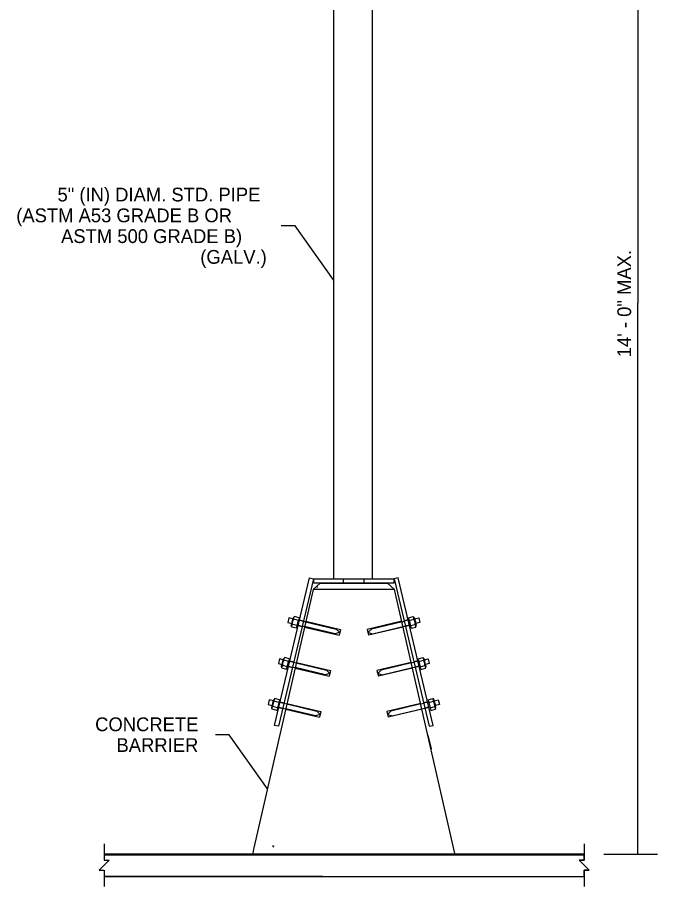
# Model space of a CAD drawing. Extents: x 99988 to 100172, y 99995 to 100047.
# Drawn here: x 100006.354 to 100009.611, y 100001.519 to 100005.936 of the extents above; entities that cross this region are included whole.
import ezdxf

# ---------------------------------------------------------------- set-up
doc = ezdxf.new("R2010")
doc.units = 0
for name, color, linetype in [('Level 1', 7, 'Continuous'), ('Level 10', 7, 'Continuous'), ('Level 12', 7, 'Continuous'), ('Level 15', 7, 'Continuous'), ('Level 18', 7, 'Continuous'), ('Level 20', 7, 'Continuous'), ('Level 8', 7, 'Continuous')]:
    doc.layers.add(name, color=color, linetype=linetype)

msp = doc.modelspace()

# ---------------------------------------------------------------- linework, layer by layer
at = {"layer": 'Level 1'}
msp.add_line((100006.796, 100001.681), (100009.2374, 100001.681), dxfattribs=at)
for points in [[(100007.9087, 100001.571), (100006.796, 100001.571)], [(100006.796, 100001.571), (100009.2374, 100001.571)]]:
    msp.add_lwpolyline(points, dxfattribs=at)
at = {"layer": 'Level 10'}
for p, q in [((100008.1604, 100003.0822), (100008.1604, 100007.3213)), ((100007.9616, 100007.3133), (100007.9616, 100003.0822))]:
    msp.add_line(p, q, dxfattribs=at)
at = {"layer": 'Level 12'}
for p, q in [((100007.8621, 100003.0822), (100008.2692, 100003.0822)), ((100007.8621, 100003.0607), (100007.8621, 100003.0822)), ((100008.0121, 100003.0822), (100008.0121, 100003.0607)), ((100008.1192, 100003.0607), (100008.1192, 100003.0822)), ((100008.2692, 100003.0822), (100008.2692, 100003.0607)), ((100008.2692, 100003.0607), (100007.8621, 100003.0607)), ((100008.1192, 100003.0607), (100008.0121, 100003.0607))]:
    msp.add_line(p, q, dxfattribs=at)
for points in [[(100007.861, 100003.0834), (100007.6826, 100002.3333), (100007.6618, 100002.3382), (100007.8401, 100003.0884)], [(100008.2703, 100003.0834), (100008.4487, 100002.3333), (100008.4695, 100002.3382), (100008.2912, 100003.0884)]]:
    msp.add_lwpolyline(points, close=True, dxfattribs=at)
at = {"layer": 'Level 15'}
for p, q in [((100009.511, 100007.2852), (100009.511, 100004.4843)), ((100009.511, 100001.6835), (100009.511, 100004.4843)), ((100009.3374, 100001.6835), (100009.611, 100001.6835))]:
    msp.add_line(p, q, dxfattribs=at)
for points in [[(100007.9616, 100004.6015), (100007.7669, 100004.8769), (100007.6969, 100004.8769)], [(100007.6262, 100002.0153), (100007.4314, 100002.2907), (100007.3614, 100002.2907)], [(100006.796, 100001.7357), (100006.796, 100001.6525), (100006.8213, 100001.6525), (100006.7707, 100001.602), (100006.796, 100001.602), (100006.796, 100001.5188)], [(100009.2374, 100001.7357), (100009.2374, 100001.6525), (100009.2122, 100001.6525), (100009.2627, 100001.602), (100009.2374, 100001.602), (100009.2374, 100001.5188)], [(100009.2374, 100001.7357), (100009.2374, 100001.6525), (100009.2122, 100001.6525), (100009.2627, 100001.602), (100009.2374, 100001.602), (100009.2374, 100001.5188)]]:
    msp.add_lwpolyline(points, dxfattribs=at)
at = {"layer": 'Level 18'}
for p, q in [((100007.9799, 100003.0822), (100008.1514, 100003.0822)), ((100008.146, 100003.0822), (100008.1514, 100003.0822)), ((100007.7352, 100002.8851), (100007.7294, 100002.8608)), ((100007.7294, 100002.8608), (100007.7501, 100002.8558)), ((100007.7562, 100002.8801), (100007.7352, 100002.8851)), ((100007.7842, 100002.8734), (100007.7887, 100002.8723)), ((100007.7887, 100002.8723), (100007.8096, 100002.8674)), ((100007.8096, 100002.8674), (100007.8206, 100002.8647)), ((100007.8206, 100002.8647), (100007.9763, 100002.8277)), ((100008.3108, 100002.8647), (100008.1551, 100002.8277)), ((100008.3108, 100002.8647), (100008.3218, 100002.8674)), ((100008.3427, 100002.8723), (100008.3218, 100002.8674)), ((100008.3472, 100002.8734), (100008.3427, 100002.8723)), ((100008.3752, 100002.8801), (100008.3963, 100002.8851)), ((100008.402, 100002.8608), (100008.3813, 100002.8558)), ((100008.3963, 100002.8851), (100008.402, 100002.8608)), ((100007.7781, 100002.8491), (100007.783, 100002.848)), ((100007.783, 100002.848), (100007.8038, 100002.843)), ((100007.8038, 100002.843), (100007.8151, 100002.8404)), ((100007.9705, 100002.8034), (100007.8151, 100002.8404)), ((100007.9915, 100002.8099), (100007.9705, 100002.8034)), ((100007.9763, 100002.8277), (100007.9921, 100002.8124)), ((100008.1551, 100002.8277), (100008.1393, 100002.8124)), ((100008.1399, 100002.8099), (100008.1609, 100002.8034)), ((100008.1609, 100002.8034), (100008.3164, 100002.8404)), ((100008.3164, 100002.8404), (100008.3276, 100002.843)), ((100008.3485, 100002.848), (100008.3276, 100002.843)), ((100008.3533, 100002.8491), (100008.3485, 100002.848)), ((100007.688, 100002.6762), (100007.6822, 100002.6519)), ((100007.6822, 100002.6519), (100007.7013, 100002.6473)), ((100007.7069, 100002.6717), (100007.688, 100002.6762)), ((100007.7285, 100002.6407), (100007.7334, 100002.6395)), ((100007.7334, 100002.6395), (100007.7542, 100002.6346)), ((100007.7346, 100002.6649), (100007.7392, 100002.6639)), ((100007.7392, 100002.6639), (100007.76, 100002.6589)), ((100007.7542, 100002.6346), (100007.7672, 100002.6315)), ((100007.76, 100002.6589), (100007.7728, 100002.6559)), ((100007.7728, 100002.6559), (100007.9268, 100002.6193)), ((100008.3586, 100002.6559), (100008.2047, 100002.6193)), ((100008.3586, 100002.6559), (100008.3714, 100002.6589)), ((100008.3642, 100002.6315), (100008.3772, 100002.6346)), ((100008.3922, 100002.6639), (100008.3714, 100002.6589)), ((100008.398, 100002.6395), (100008.3772, 100002.6346)), ((100008.3968, 100002.6649), (100008.3922, 100002.6639)), ((100008.4029, 100002.6407), (100008.398, 100002.6395)), ((100008.4245, 100002.6717), (100008.4434, 100002.6762)), ((100008.4492, 100002.6519), (100008.4302, 100002.6473)), ((100008.4434, 100002.6762), (100008.4492, 100002.6519)), ((100007.921, 100002.5949), (100007.7672, 100002.6315)), ((100007.942, 100002.6015), (100007.921, 100002.5949)), ((100007.9268, 100002.6193), (100007.9426, 100002.604)), ((100008.2047, 100002.6193), (100008.1889, 100002.604)), ((100008.1894, 100002.6015), (100008.2104, 100002.5949)), ((100008.2104, 100002.5949), (100008.3642, 100002.6315)), ((100007.636, 100002.4682), (100007.6302, 100002.4438)), ((100007.657, 100002.4632), (100007.636, 100002.4682)), ((100007.6849, 100002.4565), (100007.6894, 100002.4555)), ((100008.4466, 100002.4565), (100008.4421, 100002.4555)), ((100008.4744, 100002.4632), (100008.4954, 100002.4682)), ((100008.4954, 100002.4682), (100008.5012, 100002.4438)), ((100007.6302, 100002.4438), (100007.6509, 100002.4389)), ((100007.6786, 100002.4323), (100007.6836, 100002.4311)), ((100007.6836, 100002.4311), (100007.7044, 100002.4262)), ((100007.6894, 100002.4555), (100007.7102, 100002.4505)), ((100007.7044, 100002.4262), (100007.7194, 100002.4226)), ((100007.7102, 100002.4505), (100007.725, 100002.447)), ((100007.8712, 100002.3866), (100007.7194, 100002.4226)), ((100007.725, 100002.447), (100007.877, 100002.4109)), ((100008.4064, 100002.447), (100008.2545, 100002.4109)), ((100008.2603, 100002.3866), (100008.412, 100002.4226)), ((100008.4064, 100002.447), (100008.4212, 100002.4505)), ((100008.412, 100002.4226), (100008.427, 100002.4262)), ((100008.4421, 100002.4555), (100008.4212, 100002.4505)), ((100008.4478, 100002.4311), (100008.427, 100002.4262)), ((100008.4528, 100002.4323), (100008.4478, 100002.4311)), ((100008.5012, 100002.4438), (100008.4805, 100002.4389)), ((100007.8922, 100002.3931), (100007.8712, 100002.3866)), ((100007.877, 100002.4109), (100007.8928, 100002.3956)), ((100008.2545, 100002.4109), (100008.2387, 100002.3956)), ((100008.2393, 100002.3931), (100008.2603, 100002.3866))]:
    msp.add_line(p, q, dxfattribs=at)
for centre, start, end in [((100007.9911, 100002.8113), 287.2722, 45.9747), ((100008.1403, 100002.8113), 134.0253, 252.7278), ((100007.9415, 100002.6029), 287.2722, 45.9747), ((100008.1899, 100002.6029), 134.0253, 252.7278), ((100007.8917, 100002.3945), 287.2722, 45.9747), ((100008.2397, 100002.3945), 134.0253, 252.7278)]:
    msp.add_arc(centre, 0.0015, start, end, dxfattribs=at)
at = {"layer": 'Level 20'}
for p, q in [((100007.7477, 100002.8455), (100007.75, 100002.8545)), ((100007.7638, 100002.8912), (100007.7576, 100002.8851)), ((100007.7838, 100002.8717), (100007.7605, 100002.8775)), ((100007.7872, 100002.8853), (100007.7639, 100002.8911)), ((100007.7769, 100002.8445), (100007.7838, 100002.8719)), ((100007.7838, 100002.8717), (100007.777, 100002.8448)), ((100007.7872, 100002.8853), (100007.7838, 100002.8717)), ((100007.7871, 100002.8854), (100007.7871, 100002.8853)), ((100007.7893, 100002.8747), (100007.8102, 100002.8698)), ((100007.8212, 100002.8672), (100007.9974, 100002.8253)), ((100008.3102, 100002.8672), (100008.134, 100002.8253)), ((100008.3421, 100002.8747), (100008.3213, 100002.8698)), ((100008.3443, 100002.8853), (100008.3676, 100002.8911)), ((100008.3443, 100002.8853), (100008.3477, 100002.8717)), ((100008.3444, 100002.8854), (100008.3444, 100002.8853)), ((100008.3545, 100002.8445), (100008.3476, 100002.8719)), ((100008.3477, 100002.8717), (100008.371, 100002.8775)), ((100008.3477, 100002.8717), (100008.3544, 100002.8448)), ((100008.3676, 100002.8912), (100008.3738, 100002.8851)), ((100008.3837, 100002.8455), (100008.3815, 100002.8545)), ((100007.7736, 100002.8313), (100007.7503, 100002.8371)), ((100007.777, 100002.8448), (100007.7537, 100002.8507)), ((100007.777, 100002.8448), (100007.7736, 100002.8313)), ((100007.7736, 100002.8313), (100007.7769, 100002.8445)), ((100007.7824, 100002.8456), (100007.8032, 100002.8406)), ((100007.8145, 100002.8379), (100007.9905, 100002.7961)), ((100007.9974, 100002.8253), (100007.9905, 100002.7961)), ((100008.134, 100002.8253), (100008.1409, 100002.7961)), ((100008.3169, 100002.8379), (100008.1409, 100002.7961)), ((100008.3491, 100002.8456), (100008.3282, 100002.8406)), ((100008.3544, 100002.8448), (100008.3777, 100002.8507)), ((100008.3544, 100002.8448), (100008.3578, 100002.8313)), ((100008.3578, 100002.8313), (100008.3545, 100002.8445)), ((100008.3578, 100002.8313), (100008.3811, 100002.8371)), ((100007.7142, 100002.6827), (100007.7081, 100002.6766)), ((100007.7376, 100002.6768), (100007.7143, 100002.6827)), ((100007.7376, 100002.6768), (100007.7342, 100002.6633)), ((100007.7375, 100002.6769), (100007.7375, 100002.6768)), ((100008.3938, 100002.6768), (100008.4171, 100002.6827)), ((100008.3938, 100002.6768), (100008.3972, 100002.6633)), ((100008.3939, 100002.6769), (100008.3939, 100002.6768)), ((100008.4172, 100002.6827), (100008.4234, 100002.6766)), ((100007.6982, 100002.6371), (100007.7004, 100002.6461)), ((100007.7275, 100002.6364), (100007.7042, 100002.6422)), ((100007.7342, 100002.6633), (100007.7109, 100002.6691)), ((100007.7275, 100002.6364), (100007.7241, 100002.6228)), ((100007.7241, 100002.6228), (100007.7274, 100002.636)), ((100007.7274, 100002.636), (100007.7342, 100002.6634)), ((100007.7342, 100002.6633), (100007.7275, 100002.6364)), ((100007.7328, 100002.6371), (100007.7537, 100002.6321)), ((100007.7398, 100002.6663), (100007.7606, 100002.6613)), ((100007.7734, 100002.6583), (100007.9479, 100002.6168)), ((100008.3581, 100002.6583), (100008.1836, 100002.6168)), ((100008.3917, 100002.6663), (100008.3708, 100002.6613)), ((100008.3986, 100002.6371), (100008.3778, 100002.6321)), ((100008.3972, 100002.6633), (100008.4205, 100002.6691)), ((100008.4041, 100002.636), (100008.3972, 100002.6634)), ((100008.3972, 100002.6633), (100008.404, 100002.6364)), ((100008.404, 100002.6364), (100008.4273, 100002.6422)), ((100008.404, 100002.6364), (100008.4074, 100002.6228)), ((100008.4074, 100002.6228), (100008.4041, 100002.636)), ((100008.4333, 100002.6371), (100008.431, 100002.6461)), ((100007.7241, 100002.6228), (100007.7008, 100002.6287)), ((100007.7667, 100002.6291), (100007.9409, 100002.5876)), ((100007.9479, 100002.6168), (100007.9409, 100002.5876)), ((100008.1836, 100002.6168), (100008.1905, 100002.5876)), ((100008.3648, 100002.6291), (100008.1905, 100002.5876)), ((100008.4074, 100002.6228), (100008.4306, 100002.6287)), ((100007.6363, 100002.4694), (100007.6363, 100002.4694)), ((100007.6573, 100002.4644), (100007.6583, 100002.4682)), ((100007.6644, 100002.4744), (100007.6583, 100002.4682)), ((100007.6844, 100002.4549), (100007.6611, 100002.4607)), ((100007.6878, 100002.4684), (100007.6645, 100002.4743)), ((100007.6878, 100002.4684), (100007.6844, 100002.4549)), ((100007.6877, 100002.4685), (100007.6877, 100002.4685)), ((100007.69, 100002.4579), (100007.7108, 100002.4529)), ((100008.4415, 100002.4579), (100008.4206, 100002.4529)), ((100008.4436, 100002.4684), (100008.4669, 100002.4743)), ((100008.4436, 100002.4684), (100008.447, 100002.4549)), ((100008.4437, 100002.4685), (100008.4437, 100002.4685)), ((100008.447, 100002.4549), (100008.4703, 100002.4607)), ((100008.467, 100002.4744), (100008.4732, 100002.4682)), ((100008.4741, 100002.4644), (100008.4732, 100002.4682)), ((100008.4952, 100002.4694), (100008.4952, 100002.4694)), ((100007.6484, 100002.4287), (100007.6506, 100002.4377)), ((100007.6743, 100002.4144), (100007.651, 100002.4203)), ((100007.6777, 100002.428), (100007.6544, 100002.4338)), ((100007.6777, 100002.428), (100007.6743, 100002.4144)), ((100007.6844, 100002.4549), (100007.6777, 100002.428)), ((100007.683, 100002.4287), (100007.7039, 100002.4238)), ((100007.7189, 100002.4202), (100007.8911, 100002.3792)), ((100007.7256, 100002.4494), (100007.8981, 100002.4084)), ((100008.4059, 100002.4494), (100008.2334, 100002.4084)), ((100008.4126, 100002.4202), (100008.2403, 100002.3792)), ((100008.4484, 100002.4287), (100008.4276, 100002.4238)), ((100008.447, 100002.4549), (100008.4538, 100002.428)), ((100008.4538, 100002.428), (100008.4771, 100002.4338)), ((100008.4538, 100002.428), (100008.4572, 100002.4144)), ((100008.4572, 100002.4144), (100008.4804, 100002.4203)), ((100008.4831, 100002.4287), (100008.4808, 100002.4377)), ((100007.8981, 100002.4084), (100007.8911, 100002.3792)), ((100008.2334, 100002.4084), (100008.2403, 100002.3792))]:
    msp.add_line(p, q, dxfattribs=at)
msp.add_lwpolyline([(100007.9087, 100001.571), (100009.2374, 100001.571), (100009.2374, 100001.602), (100009.2627, 100001.602), (100009.2122, 100001.6525), (100009.2374, 100001.6525), (100009.2374, 100001.6835), (100008.9538, 100001.6835), (100008.7339, 100001.6835), (100008.367, 100001.6835), (100007.6568, 100001.6835), (100007.2898, 100001.6835), (100007.1618, 100001.6835), (100006.796, 100001.6835), (100006.796, 100001.6525), (100006.8213, 100001.6525), (100006.7707, 100001.602), (100006.796, 100001.602), (100006.796, 100001.571), (100007.9087, 100001.571)], dxfattribs=at)
for points, degree in [([(100007.75, 100002.8545), (100007.75, 100002.8545), (100007.7567, 100002.8812), (100007.7576, 100002.8851), (100007.7567, 100002.8812), (100007.75, 100002.8545), (100007.75, 100002.8545)], 4), ([(100007.7537, 100002.8507), (100007.7535, 100002.8554), (100007.7538, 100002.86), (100007.7561, 100002.8692), (100007.7581, 100002.8735), (100007.7605, 100002.8775)], 3), ([(100007.7605, 100002.8775), (100007.7597, 100002.8801), (100007.7594, 100002.8825), (100007.7606, 100002.8872), (100007.762, 100002.8892), (100007.7639, 100002.8911)], 3), ([(100007.7605, 100002.8775), (100007.7597, 100002.8801), (100007.7594, 100002.8825), (100007.7606, 100002.8872), (100007.762, 100002.8892), (100007.7639, 100002.8911)], 3), ([(100008.371, 100002.8775), (100008.3717, 100002.8801), (100008.372, 100002.8825), (100008.3709, 100002.8872), (100008.3694, 100002.8892), (100008.3676, 100002.8911)], 3), ([(100008.371, 100002.8775), (100008.3717, 100002.8801), (100008.372, 100002.8825), (100008.3709, 100002.8872), (100008.3694, 100002.8892), (100008.3676, 100002.8911)], 3), ([(100008.3777, 100002.8507), (100008.3779, 100002.8554), (100008.3776, 100002.86), (100008.3754, 100002.8692), (100008.3734, 100002.8735), (100008.371, 100002.8775)], 3), ([(100008.3815, 100002.8545), (100008.3815, 100002.8545), (100008.3748, 100002.8812), (100008.3738, 100002.8851), (100008.3748, 100002.8812), (100008.3815, 100002.8545), (100008.3815, 100002.8545)], 4), ([(100007.7502, 100002.8373), (100007.7494, 100002.84), (100007.7486, 100002.8428), (100007.7477, 100002.8455)], 2), ([(100007.7503, 100002.8371), (100007.7496, 100002.8396), (100007.7493, 100002.8421), (100007.7504, 100002.8467), (100007.7518, 100002.8488), (100007.7537, 100002.8507)], 3), ([(100007.7503, 100002.8371), (100007.7496, 100002.8396), (100007.7493, 100002.8421), (100007.7504, 100002.8467), (100007.7518, 100002.8488), (100007.7537, 100002.8507)], 3), ([(100008.3811, 100002.8371), (100008.3819, 100002.8396), (100008.3822, 100002.8421), (100008.381, 100002.8467), (100008.3796, 100002.8488), (100008.3777, 100002.8507)], 3), ([(100008.3811, 100002.8371), (100008.3819, 100002.8396), (100008.3822, 100002.8421), (100008.381, 100002.8467), (100008.3796, 100002.8488), (100008.3777, 100002.8507)], 3), ([(100008.3812, 100002.8373), (100008.382, 100002.84), (100008.3829, 100002.8428), (100008.3837, 100002.8455)], 2), ([(100007.7109, 100002.6691), (100007.7101, 100002.6716), (100007.7098, 100002.6741), (100007.711, 100002.6787), (100007.7124, 100002.6808), (100007.7143, 100002.6827)], 3), ([(100007.7109, 100002.6691), (100007.7101, 100002.6716), (100007.7098, 100002.6741), (100007.711, 100002.6787), (100007.7124, 100002.6808), (100007.7143, 100002.6827)], 3), ([(100008.4205, 100002.6691), (100008.4213, 100002.6716), (100008.4216, 100002.6741), (100008.4204, 100002.6787), (100008.419, 100002.6808), (100008.4171, 100002.6827)], 3), ([(100008.4205, 100002.6691), (100008.4213, 100002.6716), (100008.4216, 100002.6741), (100008.4204, 100002.6787), (100008.419, 100002.6808), (100008.4171, 100002.6827)], 3), ([(100007.7007, 100002.6289), (100007.6998, 100002.6316), (100007.699, 100002.6343), (100007.6982, 100002.6371)], 2), ([(100007.7008, 100002.6287), (100007.7, 100002.6312), (100007.6997, 100002.6337), (100007.7009, 100002.6383), (100007.7023, 100002.6403), (100007.7042, 100002.6422)], 3), ([(100007.7008, 100002.6287), (100007.7, 100002.6312), (100007.6997, 100002.6337), (100007.7009, 100002.6383), (100007.7023, 100002.6403), (100007.7042, 100002.6422)], 3), ([(100007.7004, 100002.6461), (100007.7004, 100002.6461), (100007.7033, 100002.6578), (100007.7081, 100002.6766)], 3), ([(100007.7042, 100002.6422), (100007.704, 100002.6469), (100007.7042, 100002.6516), (100007.7065, 100002.6607), (100007.7085, 100002.665), (100007.7109, 100002.6691)], 3), ([(100007.7046, 100002.6627), (100007.7046, 100002.6626), (100007.7046, 100002.6626), (100007.7046, 100002.6626)], 3), ([(100008.4273, 100002.6422), (100008.4275, 100002.6469), (100008.4272, 100002.6516), (100008.4249, 100002.6607), (100008.4229, 100002.665), (100008.4205, 100002.6691)], 3), ([(100008.431, 100002.6461), (100008.431, 100002.6461), (100008.4281, 100002.6578), (100008.4234, 100002.6766)], 3), ([(100008.4269, 100002.6627), (100008.4269, 100002.6626), (100008.4269, 100002.6626), (100008.4269, 100002.6626)], 3), ([(100008.4306, 100002.6287), (100008.4314, 100002.6312), (100008.4317, 100002.6337), (100008.4306, 100002.6383), (100008.4291, 100002.6403), (100008.4273, 100002.6422)], 3), ([(100008.4306, 100002.6287), (100008.4314, 100002.6312), (100008.4317, 100002.6337), (100008.4306, 100002.6383), (100008.4291, 100002.6403), (100008.4273, 100002.6422)], 3), ([(100008.4308, 100002.6289), (100008.4316, 100002.6316), (100008.4324, 100002.6343), (100008.4333, 100002.6371)], 2), ([(100007.6506, 100002.4377), (100007.6506, 100002.4377), (100007.6573, 100002.4644), (100007.6573, 100002.4644), (100007.6573, 100002.4644), (100007.6506, 100002.4377), (100007.6506, 100002.4377)], 4), ([(100007.6544, 100002.4338), (100007.6542, 100002.4385), (100007.6544, 100002.4432), (100007.6567, 100002.4524), (100007.6587, 100002.4567), (100007.6611, 100002.4607)], 3), ([(100007.6611, 100002.4607), (100007.6603, 100002.4633), (100007.66, 100002.4657), (100007.6612, 100002.4703), (100007.6626, 100002.4724), (100007.6645, 100002.4743)], 3), ([(100007.6611, 100002.4607), (100007.6603, 100002.4633), (100007.66, 100002.4657), (100007.6612, 100002.4703), (100007.6626, 100002.4724), (100007.6645, 100002.4743)], 3), ([(100008.4703, 100002.4607), (100008.4711, 100002.4633), (100008.4714, 100002.4657), (100008.4702, 100002.4703), (100008.4688, 100002.4724), (100008.4669, 100002.4743)], 3), ([(100008.4703, 100002.4607), (100008.4711, 100002.4633), (100008.4714, 100002.4657), (100008.4702, 100002.4703), (100008.4688, 100002.4724), (100008.4669, 100002.4743)], 3), ([(100008.4771, 100002.4338), (100008.4773, 100002.4385), (100008.477, 100002.4432), (100008.4747, 100002.4524), (100008.4727, 100002.4567), (100008.4703, 100002.4607)], 3), ([(100008.4808, 100002.4377), (100008.4808, 100002.4377), (100008.4741, 100002.4644), (100008.4741, 100002.4644), (100008.4741, 100002.4644), (100008.4808, 100002.4377), (100008.4808, 100002.4377)], 4), ([(100007.6509, 100002.4205), (100007.65, 100002.4232), (100007.6492, 100002.4259), (100007.6484, 100002.4287)], 2), ([(100007.651, 100002.4203), (100007.6502, 100002.4228), (100007.6499, 100002.4253), (100007.6511, 100002.4299), (100007.6525, 100002.4319), (100007.6544, 100002.4338)], 3), ([(100007.651, 100002.4203), (100007.6502, 100002.4228), (100007.6499, 100002.4253), (100007.6511, 100002.4299), (100007.6525, 100002.4319), (100007.6544, 100002.4338)], 3), ([(100008.4804, 100002.4203), (100008.4812, 100002.4228), (100008.4815, 100002.4253), (100008.4804, 100002.4299), (100008.479, 100002.4319), (100008.4771, 100002.4338)], 3), ([(100008.4804, 100002.4203), (100008.4812, 100002.4228), (100008.4815, 100002.4253), (100008.4804, 100002.4299), (100008.479, 100002.4319), (100008.4771, 100002.4338)], 3), ([(100008.4806, 100002.4205), (100008.4814, 100002.4232), (100008.4822, 100002.4259), (100008.4831, 100002.4287)], 2)]:
    msp.add_open_spline(points, degree=degree, dxfattribs=at)
at = {"layer": 'Level 8'}
for p, q in [((100007.8582, 100003.0286), (100007.8943, 100003.0605)), ((100007.8943, 100003.0605), (100007.8774, 100003.0455)), ((100007.8825, 100003.0391), (100007.8774, 100003.0455)), ((100007.8943, 100003.0605), (100008.2371, 100003.0605)), ((100008.254, 100003.0456), (100008.2371, 100003.0605)), ((100008.2371, 100003.0605), (100008.2733, 100003.0286)), ((100008.2733, 100003.0286), (100007.8582, 100003.0286)), ((100008.4426, 100002.289), (100008.4587, 100002.2189)), ((100007.6544, 100001.7282), (100007.653, 100001.7223)), ((100007.6567, 100001.7259), (100007.6553, 100001.7199))]:
    msp.add_line(p, q, dxfattribs=at)
msp.add_lwpolyline([(100007.8582, 100003.0286), (100007.5574, 100001.7152), (100007.5561, 100001.7092), (100007.5515, 100001.6892), (100007.5496, 100001.681), (100008.5818, 100001.681), (100008.2733, 100003.0286), (100008.254, 100003.0456), (100008.2371, 100003.0605), (100007.8943, 100003.0605), (100007.8582, 100003.0286)], dxfattribs=at)

# ---------------------------------------------------------------- texts
at = {"layer": 'Level 20'}
for s, p in [('5" (IN) DIAM. STD. PIPE', (100006.5586, 100005.0003)), ('(ASTM A53 GRADE B OR', (100006.3487, 100004.8947)), ('ASTM 500 GRADE B)', (100006.5768, 100004.7891)), ('(GALV.)', (100007.2849, 100004.6836)), ('CONCRETE', (100006.7501, 100002.3085)), ('BARRIER', (100006.8586, 100002.203))]:
    msp.add_text(s, height=0.07, dxfattribs=at).set_placement(p)
msp.add_text('14\' - 0" MAX.', height=0.07, rotation=90, dxfattribs=at).set_placement((100009.476, 100004.2086))

doc.saveas('drawing.dxf')
